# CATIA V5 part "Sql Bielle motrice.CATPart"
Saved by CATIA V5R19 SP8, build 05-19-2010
Part number: Sql Bielle motrice
Publications: "Droite.1", "Point.3", "Plan.1", "Plan.2"
Bounding box of the stored display mesh (mm): x 0 to 0, y -250 to -250, z -1300 to -100
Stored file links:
  G:\EU_thinkMotion\CFAO_2010\MMS_groupe3\MMS_groupe3\rdalborgo\rdalborgo\Sql Bielle motrice.CATPart
  G:\EU_thinkMotion\CFAO_2010\MMS_groupe3\MMS_groupe3\rdalborgo\rdalborgo\rdalborgo.CATProduct
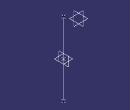
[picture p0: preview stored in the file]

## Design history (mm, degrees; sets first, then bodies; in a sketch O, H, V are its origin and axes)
Set1
  Point1 "A bielle": linked copy from another document
  Point2 "D bielle": linked copy from another document
  Plane1: linked copy from another document
Set2
  Line1: type PtPt, FirstPoint Point1, SecondPoint Point2
  Point3: type OnCurve, Support Line1, Ratio 0.5
  Plane2: type Normal, Curve Line1, RefPoint Point3
  Plane3: type OffsetPt, RefPlane Plane1, RefPoint Point3
Body1 (main body)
